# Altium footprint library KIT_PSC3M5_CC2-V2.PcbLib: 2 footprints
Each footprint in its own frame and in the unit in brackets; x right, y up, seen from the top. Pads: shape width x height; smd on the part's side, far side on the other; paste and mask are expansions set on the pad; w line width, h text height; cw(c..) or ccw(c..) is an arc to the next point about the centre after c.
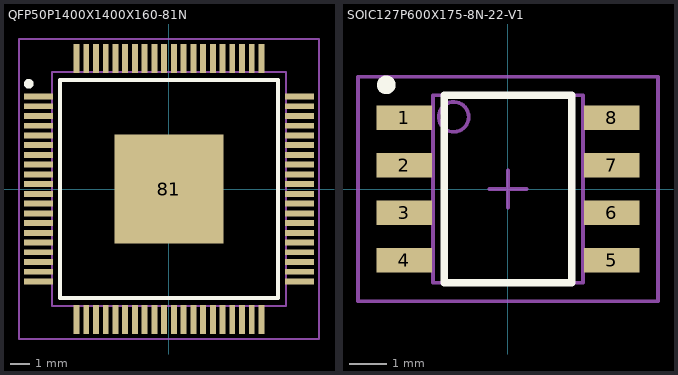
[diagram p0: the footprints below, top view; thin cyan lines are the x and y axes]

## QFP50P1400X1400X160-81N [mm] "QFP,0.50mm pitch,square;80 pin,12.00mm L X 12.00mm W X 1.60mm H body (w/thermal tab)"
height 1.6
pads (81):
  rect 1.5x0.3 smd paste+0 mask+0: 1(-6.7,4.75) 2(-6.7,4.25) 3(-6.7,3.75) 4(-6.7,3.25) 5(-6.7,2.75) 6(-6.7,2.25) 7(-6.7,1.75) 8(-6.7,1.25) 9(-6.7,0.75) 10(-6.7,0.25) 11(-6.7,-0.25) 12(-6.7,-0.75) 13(-6.7,-1.25) 14(-6.7,-1.75) 15(-6.7,-2.25) 16(-6.7,-2.75) 17(-6.7,-3.25) 18(-6.7,-3.75) 19(-6.7,-4.25) 20(-6.7,-4.75) 41(6.7,-4.75) 42(6.7,-4.25) 43(6.7,-3.75) 44(6.7,-3.25) 45(6.7,-2.75) 46(6.7,-2.25) 47(6.7,-1.75) 48(6.7,-1.25) 49(6.7,-0.75) 50(6.7,-0.25) 51(6.7,0.25) 52(6.7,0.75) 53(6.7,1.25) 54(6.7,1.75) 55(6.7,2.25) 56(6.7,2.75) 57(6.7,3.25) 58(6.7,3.75) 59(6.7,4.25) 60(6.7,4.75)
  rect 0.3x1.5 smd paste+0 mask+0: 21(-4.75,-6.7) 22(-4.25,-6.7) 23(-3.75,-6.7) 24(-3.25,-6.7) 25(-2.75,-6.7) 26(-2.25,-6.7) 27(-1.75,-6.7) 28(-1.25,-6.7) 29(-0.75,-6.7) 30(-0.25,-6.7) 31(0.25,-6.7) 32(0.75,-6.7) 33(1.25,-6.7) 34(1.75,-6.7) 35(2.25,-6.7) 36(2.75,-6.7) 37(3.25,-6.7) 38(3.75,-6.7) 39(4.25,-6.7) 40(4.75,-6.7) 61(4.75,6.7) 62(4.25,6.7) 63(3.75,6.7) 64(3.25,6.7) 65(2.75,6.7) 66(2.25,6.7) 67(1.75,6.7) 68(1.25,6.7) 69(0.75,6.7) 70(0.25,6.7) 71(-0.25,6.7) 72(-0.75,6.7) 73(-1.25,6.7) 74(-1.75,6.7) 75(-2.25,6.7) 76(-2.75,6.7) 77(-3.25,6.7) 78(-3.75,6.7) 79(-4.25,6.7) 80(-4.75,6.7)
  rect 5.6x5.6 smd paste+0 mask+0: 81(0,0)
Top Overlay:
  circle w0.25: c-7.2,5.4 r0.125
  lines w0.2: -5.6,-5.6 -5.6,5.6 5.6,5.6 5.6,-5.6 -5.6,-5.6
M3 (ASY_Text_Top):
  text ".DESIGNATOR" at 0,0 h1.2
M13 (CMP_Body_OTL_Top):
  lines w0.1: -6,-6 -6,6 6,6 6,-6 -6,-6
M15 (CMP_Courtyard_Top):
  lines w0.1: -0.5,0 0.5,0 ; 0,-0.5 0,0.5 ; -7.7,-7.7 -7.7,7.7 7.7,7.7 7.7,-7.7 -7.7,-7.7
3D body "LQFP-80-2.stp": height 1.61, standoff 0, extent -7,-7 7,7

## SOIC127P600X175-8N-22-V1 [mm] "SOIC,1.27mm pitch;8 pin,3.90mm W X 4.90mm L X 1.75mm H body"
height 1.75
pads (8):
  rect 1.47x0.65 smd paste+0 mask+0: 1(-2.77,1.905) 2(-2.77,0.635) 3(-2.77,-0.635) 4(-2.77,-1.905) 5(2.77,-1.905) 6(2.77,-0.635) 7(2.77,0.635) 8(2.77,1.905)
Top Overlay:
  circle w0.25: c-3.25,2.78 r0.125
  lines w0.2: -1.7,-2.5 -1.7,2.5 1.7,2.5 1.7,-2.5 -1.7,-2.5
M3 (ASY_Text_Top):
  text ".DESIGNATOR" at 0,0 h1.2
M13 (CMP_Body_OTL_Top):
  circle w0.1: c-1.45,1.925 r0.4
  lines w0.1: -2,-2.5 -2,2.5 2,2.5 2,-2.5 -2,-2.5
M15 (CMP_Courtyard_Top):
  lines w0.1: -0.5,0 0.5,0 ; 0,-0.5 0,0.5 ; -4.005,-3 4.005,-3 4.005,3 -4.005,3 -4.005,-3
3D body "PG-DSO-8-82.STEP": height 1.75, standoff 0, extent -3,-2.5 3,2.5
